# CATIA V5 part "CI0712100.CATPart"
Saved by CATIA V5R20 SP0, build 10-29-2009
Part number: CI0712100
Bounding box of the stored display mesh (mm): x -12 to 12, y -11.988 to 14.27, z -118 to 10.279
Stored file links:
  C:\Users\Raffaele\Desktop\3D X SITO CF\BOLEX\19-INCLINED ASSEMBLY REF_CI\CI0712100.CATPart
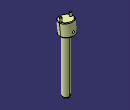
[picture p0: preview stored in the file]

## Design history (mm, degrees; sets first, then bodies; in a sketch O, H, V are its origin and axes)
Set1
  DatumSurface1 to DatumSurface16 "MANIFOLD_SOLID_BREP #380"
  DatumSurface17 to DatumSurface39 "MANIFOLD_SOLID_BREP #1097"
Body1 (main body)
